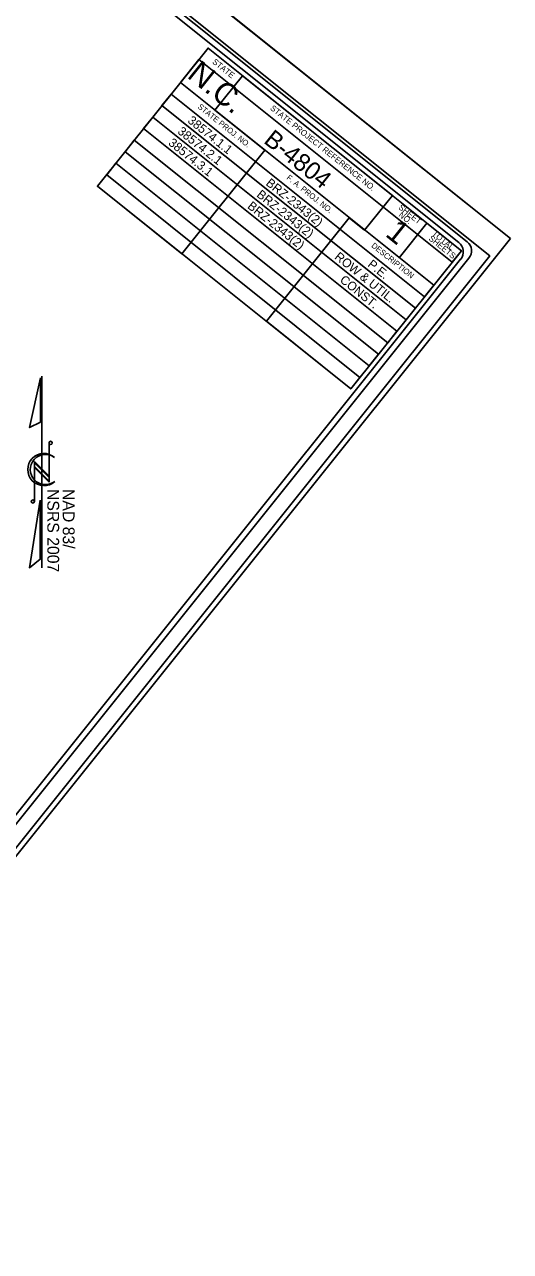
# Model space of a CAD drawing. Extents: x 1732765 to 1738218, y 913652 to 917906.
# Drawn here: x 1735946 to 1736769, y 913906 to 915987 of the extents above; entities that cross this region are included whole.
import ezdxf

# ---------------------------------------------------------------- set-up
doc = ezdxf.new("R2010")
doc.units = 0
for name, color, linetype in [('Sheet Cutting Line CELL', 7, 'Continuous'), ('Sheet Data Field CELL', 7, 'Continuous'), ('Sheet North Arrow CELL', 7, 'Continuous'), ('Sheet Plot Border Inside CELL', 7, 'Continuous'), ('Sheet Title CELL', 7, 'Continuous')]:
    doc.layers.add(name, color=color, linetype=linetype)

msp = doc.modelspace()

# ---------------------------------------------------------------- linework, layer by layer
at = {"layer": 'Sheet Cutting Line CELL'}
msp.add_line((1734139.9, 917728.5), (1736769.5, 915624), dxfattribs=at)
at = {"layer": 'Sheet Data Field CELL'}
msp.add_lwpolyline([(1736769.5, 915624), (1734139.9, 917728.5), (1732765.3, 916010.8), (1735394.8, 913906.4)], close=True, dxfattribs=at)
at = {"layer": 'Sheet North Arrow CELL'}
for p, q in [((1735975.2, 915065.8), (1735975.2, 915390.8)), ((1735987.5, 915277.7), (1735987.5, 915211)), ((1735987.5, 915221.4), (1735962.6, 915246.2)), ((1735962.6, 915246.2), (1735962.6, 915178.4)), ((1735987.5, 915218.9), (1735962.6, 915243.8)), ((1735962.6, 915243.8), (1735962.6, 915237.7)), ((1735987.5, 915212.8), (1735962.6, 915237.7)), ((1735962.6, 915237.7), (1735987.5, 915212.8)), ((1735987.5, 915211), (1735962.6, 915235.8)), ((1735996.7, 915252.8), (1735997, 915252.6)), ((1735987.5, 915212.8), (1735987.5, 915218.9))]:
    msp.add_line(p, q, dxfattribs=at)
for points in [[(1735973, 915387.9), (1735954.4, 915303.5), (1735973, 915312.9)], [(1735972.6, 915180.3), (1735954.2, 915065.8), (1735972.6, 915080.3)]]:
    msp.add_lwpolyline(points, close=True, dxfattribs=at)
for centre in [(1735990.1, 915277.6), (1735960, 915178.3)]:
    msp.add_circle(centre, 2.65, dxfattribs=at)
for centre, radius, start, end in [((1735978.7, 915232.4), 27.3, 47.84, 312.3941), ((1735981.3, 915232.4), 25.6, 53.095, 308.6287)]:
    msp.add_arc(centre, radius, start, end, dxfattribs=at)
at = {"layer": 'Sheet Plot Border Inside CELL'}
msp.add_lwpolyline([(1732813.6, 916029.6), (1735415.9, 913947), (1736734.4, 915594.6), (1734132.1, 917677.2)], close=True, dxfattribs=at)
at = {"layer": 'Sheet Title CELL'}
for points in [[(1736696.1, 915618.7), (1734385, 917468.3)], [(1736682, 915617.2), (1734464.7, 917391.7)], [(1736069.5, 915712.9), (1736498.9, 915369.2), (1736514.5, 915388.7), (1736085.2, 915732.4), (1736100.8, 915751.9), (1736530.2, 915408.2), (1736545.8, 915427.8), (1736116.4, 915771.4), (1736132, 915791), (1736561.4, 915447.3), (1736577, 915466.8), (1736147.6, 915810.5), (1736163.2, 915830), (1736592.7, 915486.3), (1736608.3, 915505.8), (1736178.9, 915849.5), (1736194.5, 915869), (1736623.9, 915525.3), (1736639.5, 915544.9), (1736210.1, 915888.5), (1736241.4, 915927.6), (1736670.8, 915583.9), (1736686.4, 915603.4), (1736257, 915947.1), (1736069.5, 915712.9), (1736212.6, 915598.3), (1736353.2, 915774), (1736268.7, 915841.7), (1736315.5, 915900.2), (1736569.3, 915697.1), (1736522.4, 915638.6), (1736496.3, 915659.5), (1736355.8, 915483.8), (1736498.9, 915369.2), (1736686.4, 915603.4), (1736627.8, 915650.3), (1736581, 915591.7)], [(1735412, 913982.3), (1736699.2, 915590.6)], [(1735641.6, 914285.2), (1736685.1, 915589.1)]]:
    msp.add_lwpolyline(points, dxfattribs=at)
for centre in [(1736669.6, 915601.6), (1736683.6, 915603.2)]:
    msp.add_arc(centre, 20, 321.3297, 51.3297, dxfattribs=at)

# ---------------------------------------------------------------- texts
at = {"layer": 'Sheet Data Field CELL'}
for s, height, p in [('38574.1.1', 15, (1736221.1, 915822)), ('38574.2.1', 15, (1736204.1, 915803.6)), ('B-4804', 30, (1736349.6, 915787.6)), ('38574.3.1', 15, (1736188.5, 915784.1)), ('BRZ-2343(2)', 15, (1736353.7, 915715.9)), ('BRZ-2343(2)', 15, (1736338.1, 915696.4)), ('BRZ-2343(2)', 15, (1736322.5, 915676.9)), ('ROW & UTIL.', 15, (1736470.2, 915590.9)), ('P.E.', 15, (1736526.3, 915578)), ('CONST.', 15, (1736479.1, 915551.7))]:
    msp.add_text(s, height=height, rotation=321.3297, dxfattribs=at).set_placement(p)
at = {"layer": 'Sheet North Arrow CELL'}
for s, p in [('NSRS 2007', (1735984.6, 915199.4)), ('NAD 83/', (1736010.8, 915199.4))]:
    msp.add_text(s, height=20, rotation=270, dxfattribs=at).set_placement(p)
at = {"layer": 'Sheet Title CELL'}
for s, height, p in [('N.C.', 38.7, (1736219.8, 915898.3)), ('STATE', 10, (1736263.3, 915922.2)), ('STATE PROJ. NO.', 9.6, (1736238.7, 915846)), ('STATE PROJECT REFERENCE NO.', 10, (1736361.4, 915843.6)), ('F. A. PROJ. NO.', 9.6, (1736389.1, 915725.7)), ('SHEET', 10, (1736578.7, 915675.5)), ('NO.', 10, (1736579, 915662.6)), ('1', 38.7, (1736555.7, 915629.5)), ('TOTAL', 10, (1736635.7, 915630.8)), ('DESCRIPTION', 9.6, (1736532.9, 915610.6)), ('SHEETS', 10, (1736630, 915622.6))]:
    msp.add_text(s, height=height, rotation=321.3297, dxfattribs=at).set_placement(p)

doc.saveas('drawing.dxf')
